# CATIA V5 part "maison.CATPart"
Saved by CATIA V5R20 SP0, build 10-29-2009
Part number: Pièce1
Bounding box of the stored display mesh (mm): x -800.909 to 0, y -110 to 1110, z -0.1 to 593.649
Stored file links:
  C:\Users\bouza\OneDrive\Bureau\bouthaina\maison.CATPart
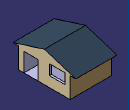
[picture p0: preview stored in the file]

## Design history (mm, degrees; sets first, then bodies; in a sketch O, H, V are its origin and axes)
Body1 (main body)
  Sketch1 on yz-plane, origin (0, 0, 0), H (0, 1, 0), V (0, 0, 1)
    line L1 (0, 0) -> (1000, 0)
    line L2 (0, 0) -> (0, 400)
    line L3 (1000, 0) -> (1000, 400)
    line L4 (0, 400) -> (-110, 400)
    line L5 (-110, 400) -> (500, 593.6492)
    line L6 (500, 593.6492) -> (1110, 400)
    line L7 (1110, 400) -> (1000, 400)
    length L1 = 1000
    length L3 = 400
    length L2 = 400
    length L5 = 640
    length L6 = 640
    length L4 = 110
    length L7 = 110
    horizontal: L1 H, L4 H, L7 H
    vertical: L2 V, L3 V
  Pad1: profile Sketch1, direction (-1, 0, 0), length 800
  Sketch2 on start face of Pad1, origin (0, 0, 0), H (0, 1, 0), V (0, 0, 1)
    point P1 (105, 0)
    line L1 (105, 0) -> (375, 0)
    line L2 (375, 0) -> (375, 360)
    line L3 (375, 360) -> (105, 360)
    line L4 (105, 360) -> (105, 0)
    reference projected line E1 (0, 400) -> (0, 0) from edge [face of Pad1 from Sketch1.L2 | start face of Pad1]
    length L4 = 360
    length L1 = 270
    distance L4 E1 = 105
    coincidence: P1 H
    horizontal: L1 H, L3 H
    vertical: L2 V, L4 V
  Pocket1: profile Sketch2, direction (-1, 0, 0), length 780
  Sketch3 on start face of Pad1, origin (0, 0, 0), H (0, 1, 0), V (0, 0, 1)
    line L1 (600, 200) -> (900, 200)
    line L2 (900, 200) -> (900, 400)
    line L3 (900, 400) -> (600, 400)
    line L4 (600, 400) -> (600, 200)
    horizontal: L1 H, L3 H
    vertical: L2 V, L4 V
  Pocket2: profile Sketch3, direction (-1, 0, 0), length 40
  Sketch4 on face of Pocket1, origin (-780, 0, 0), H (0, 1, 0), V (0, 0, 1)
    line L1 (391.0662, 386.6376) -> (601.272, 386.6376)
    line L2 (601.272, 386.6376) -> (601.272, 209.5157)
    line L3 (601.272, 209.5157) -> (391.0662, 209.5157)
    line L4 (391.0662, 209.5157) -> (391.0662, 386.6376)
    horizontal: L1 H, L3 H
    vertical: L2 V, L4 V
  Pocket3: profile Sketch4, direction (1, 0, 0), length 42
  Sketch5 on face of Pocket3, origin (-780, 0, 0), H (0, 1, 0), V (0, 0, 1)
    line L1 (397.4996, 305.4359) -> (598.2442, 305.4359)
    line L2 (598.2442, 305.4359) -> (598.2442, 202.5547)
    line L3 (598.2442, 202.5547) -> (397.4996, 202.5547)
    line L4 (397.4996, 202.5547) -> (397.4996, 305.4359)
    horizontal: L1 H, L3 H
    vertical: L2 V, L4 V
  Pocket4: profile Sketch5, direction (1, 0, 0), length 42
  Sketch6 on face of Pad1, origin (0, 0, 0), H (1, 0, 0), V (0, -1, 0)
    line L1 (-791.8029, -1752.3107) -> (776.3294, -1752.3107)
    line L2 (776.3294, -1752.3107) -> (776.3294, -1007.7247)
    line L3 (776.3294, -1007.7247) -> (-21.6961, -1007.7247)
    line L4 (-21.6961, -1007.7247) -> (-21.6961, -16.0709)
    line L5 (-21.6961, -16.0709) -> (-791.8029, -16.0709)
    line L6 (-791.8029, -16.0709) -> (-791.8029, -1752.3107)
    horizontal: L1 H, L3 H, L5 H
    vertical: L2 V, L4 V, L6 V
  Set1
    Sketch7 on start face of Pad1, origin (0, 0, 0), H (0, 1, 0), V (0, 0, 1)
      point P1 (461.1731, 188.5362)
  Sketch8 on face of Pad1, origin (0, 0, 0), H (1, 0, 0), V (0, -1, 0)
    line L1 (-40, -500) -> (-590, -500)
    line L2 (-590, -500) -> (-590, -520)
    line L3 (-590, -520) -> (-40, -520)
    line L4 (-40, -520) -> (-40, -500)
    horizontal: L1 H, L3 H
    vertical: L2 V, L4 V
  Pad2: profile Sketch8, direction (0, 0, 1), length 500
  Sketch9 on face of Pad2, origin (0, 0, 0), H (1, 0, 0), V (0, -1, 0)
    point P1 (-800.9094, 0)
    line L1 (-800.9094, 0) -> (0, 0)
    line L2 (0, 0) -> (0, -993.6947)
    line L3 (0, -993.6947) -> (-800.9094, -993.6947)
    line L4 (-800.9094, -993.6947) -> (-800.9094, 0)
    point P3 (0, -993.6947)
    coincidence: P1 H, P3 V
    horizontal: L1 H, L3 H
    vertical: L2 V, L4 V
  Pad3: profile Sketch9, direction (0, 0, -1), length 0.1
